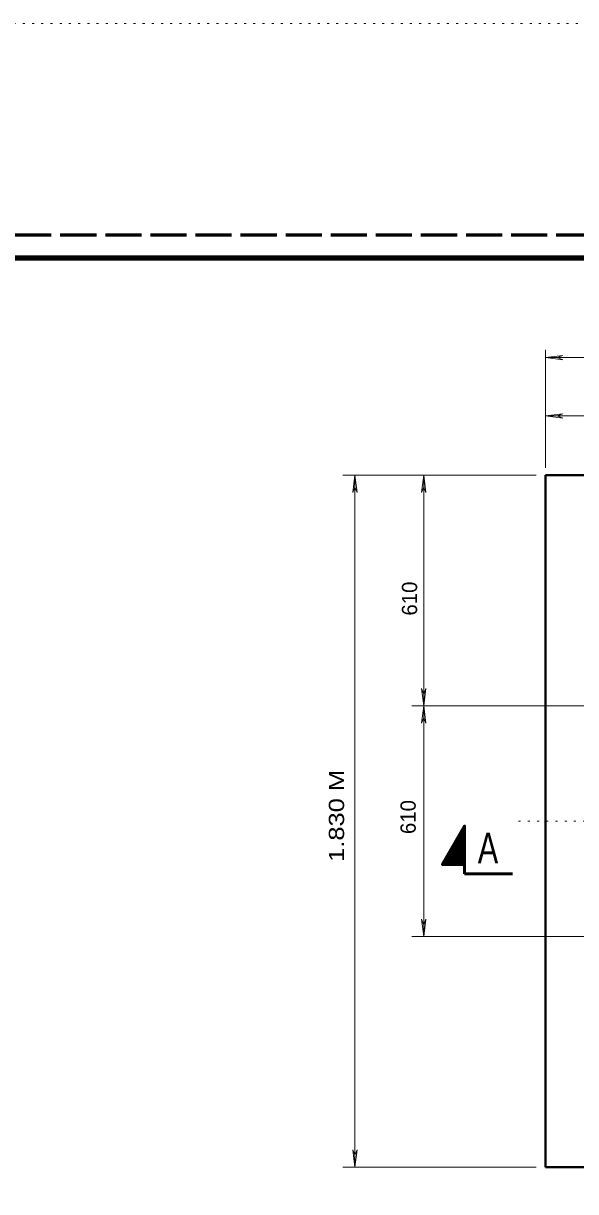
# Model space of a CAD drawing. Extents: x 312583 to 312854, y 144419 to 144597.
# Drawn here: x 312717.6 to 312745.2, y 144538.5 to 144596.8 of the extents above; entities that cross this region are included whole.
import ezdxf
from ezdxf.enums import TextEntityAlignment as Align

# ---------------------------------------------------------------- set-up
doc = ezdxf.new("R2010")
doc.units = 0
doc.header["$LTSCALE"] = 0.3
doc.linetypes.add('DOTTED', pattern=[1.5, 0.3, -1.2])
doc.linetypes.add('LONG_DASHED', pattern=[7.5, 6, -1.5])
for name, color, linetype, lineweight in [('1', 7, 'Continuous', 40), ('2', 7, 'Continuous', 13), ('62', 7, 'DOTTED', 13), ('63', 7, 'LONG_DASHED', 60)]:
    doc.layers.add(name, color=color, linetype=linetype, lineweight=lineweight)

msp = doc.modelspace()

# ---------------------------------------------------------------- linework, layer by layer
at = {"layer": '1'}
for p, q in [((312743.6593, 144574.2486), (312772.4093, 144574.2486)), ((312743.6593, 144574.2486), (312743.6593, 144539.7486)), ((312743.6593, 144539.7486), (312772.4093, 144539.7486))]:
    msp.add_line(p, q, dxfattribs=at)
at = {"layer": '1', "lineweight": 158}
msp.add_lwpolyline([(312616.5, 144423.1446), (312616.5, 144585.0846), (312849, 144585.0846)], dxfattribs=at)
at = {"layer": '2'}
for p, q in [((312743.6593, 144574.6243), (312743.6593, 144580.5046)), ((312743.6593, 144580.1213), (312744.5256, 144580.2286)), ((312743.6593, 144580.1213), (312772.4093, 144580.1213)), ((312743.6593, 144580.1213), (312744.5256, 144580.0139)), ((312744.5256, 144580.2286), (312744.2496, 144580.1213)), ((312744.5256, 144580.0139), (312744.2496, 144580.1213)), ((312743.6593, 144577.2079), (312744.5256, 144577.3153)), ((312743.6593, 144577.2079), (312744.5256, 144577.1006)), ((312744.5256, 144577.3153), (312744.2496, 144577.2079)), ((312744.5256, 144577.1006), (312744.2496, 144577.2079)), ((312743.1993, 144574.2486), (312733.5546, 144574.2486)), ((312734.1526, 144574.2486), (312734.0453, 144573.3823)), ((312734.1526, 144574.2486), (312734.1526, 144539.7486)), ((312734.1526, 144574.2486), (312734.26, 144573.3823)), ((312737.5873, 144574.2486), (312737.48, 144573.3823)), ((312737.5873, 144574.2486), (312737.6946, 144573.3823)), ((312734.0453, 144573.3823), (312734.1526, 144573.6583)), ((312734.26, 144573.3823), (312734.1526, 144573.6583)), ((312737.48, 144573.3823), (312737.5873, 144573.6583)), ((312737.6946, 144573.3823), (312737.5873, 144573.6583)), ((312737.48, 144563.6149), (312737.5873, 144563.3389)), ((312737.5873, 144562.7486), (312737.48, 144563.6149)), ((312737.6946, 144563.6149), (312737.5873, 144563.3389)), ((312737.5873, 144562.7486), (312737.6946, 144563.6149)), ((312751.74, 144562.7486), (312736.9893, 144562.7486)), ((312737.5873, 144562.7486), (312737.48, 144561.8823)), ((312737.5873, 144562.7486), (312737.6946, 144561.8823)), ((312737.48, 144561.8823), (312737.5873, 144562.1583)), ((312737.6946, 144561.8823), (312737.5873, 144562.1583)), ((312737.48, 144552.1149), (312737.5873, 144551.8389)), ((312737.5873, 144551.2486), (312737.48, 144552.1149)), ((312737.6946, 144552.1149), (312737.5873, 144551.8389)), ((312737.5873, 144551.2486), (312737.6946, 144552.1149)), ((312751.74, 144551.2486), (312736.9893, 144551.2486)), ((312734.0453, 144540.6149), (312734.1526, 144540.3389)), ((312734.1526, 144539.7486), (312734.0453, 144540.6149)), ((312734.26, 144540.6149), (312734.1526, 144540.3389)), ((312734.1526, 144539.7486), (312734.26, 144540.6149)), ((312743.1993, 144539.7486), (312733.5546, 144539.7486))]:
    msp.add_line(p, q, dxfattribs=at)
at = {"layer": '2', "lineweight": 35}
for p, q in [((312739.6266, 144556.4159), (312739.4733, 144556.5003)), ((312739.6266, 144556.4389), (312739.4886, 144556.5156)), ((312739.6266, 144556.4696), (312739.4963, 144556.5386)), ((312739.6266, 144556.4926), (312739.5116, 144556.5616)), ((312739.6266, 144556.5156), (312739.5193, 144556.5846)), ((312739.6266, 144556.5463), (312739.5346, 144556.5999)), ((312739.6266, 144556.5769), (312739.5423, 144556.6229)), ((312739.6266, 144556.6076), (312739.5576, 144556.6459)), ((312739.6266, 144556.6306), (312739.5653, 144556.6613)), ((312739.6266, 144556.6613), (312739.5806, 144556.6843)), ((312739.6266, 144556.6843), (312739.5883, 144556.7073)), ((312739.6266, 144556.7149), (312739.6036, 144556.7226)), ((312739.6266, 144556.7456), (312739.6113, 144556.7456)), ((312739.6266, 144555.6339), (312739.136, 144555.9176)), ((312739.6266, 144555.6646), (312739.1513, 144555.9406)), ((312739.6266, 144555.6953), (312739.159, 144555.9559)), ((312739.6266, 144555.7183), (312739.1743, 144555.9789)), ((312739.6266, 144555.7489), (312739.182, 144556.0019)), ((312739.6266, 144555.7796), (312739.1973, 144556.0173)), ((312739.6266, 144555.8026), (312739.205, 144556.0403)), ((312739.6266, 144555.8256), (312739.2203, 144556.0633)), ((312739.6266, 144555.8563), (312739.228, 144556.0863)), ((312739.6266, 144555.8869), (312739.2433, 144556.1016)), ((312739.6266, 144555.9176), (312739.2586, 144556.1246)), ((312739.6266, 144555.9406), (312739.2663, 144556.1476)), ((312739.6266, 144555.9713), (312739.2816, 144556.1629)), ((312739.6266, 144555.9943), (312739.297, 144556.1859)), ((312739.6266, 144556.0249), (312739.3046, 144556.2089)), ((312739.6266, 144556.0479), (312739.32, 144556.2243)), ((312739.6266, 144556.0786), (312739.3276, 144556.2473)), ((312739.6266, 144556.1093), (312739.343, 144556.2703)), ((312739.6266, 144556.1323), (312739.3506, 144556.2856)), ((312739.6266, 144556.1629), (312739.366, 144556.3163)), ((312739.6266, 144556.1859), (312739.3736, 144556.3316)), ((312739.6266, 144556.2166), (312739.389, 144556.3546)), ((312739.6266, 144556.2473), (312739.3966, 144556.3776)), ((312739.6266, 144556.2703), (312739.412, 144556.3929)), ((312739.6266, 144556.3009), (312739.4196, 144556.4159)), ((312739.6266, 144556.3239), (312739.435, 144556.4389)), ((312739.6266, 144556.3546), (312739.4503, 144556.4543)), ((312739.6266, 144556.3853), (312739.458, 144556.4773)), ((312739.6036, 144554.8443), (312738.791, 144555.3196)), ((312739.6266, 144554.8596), (312738.8063, 144555.3349)), ((312739.6266, 144554.8903), (312738.814, 144555.3579)), ((312739.6266, 144554.9209), (312738.8293, 144555.3809)), ((312739.6266, 144554.9439), (312738.837, 144555.3963)), ((312739.6266, 144554.9746), (312738.8523, 144555.4193)), ((312739.619, 144554.9976), (312738.86, 144555.4423)), ((312739.619, 144555.0283), (312738.8753, 144555.4576)), ((312739.6266, 144555.0513), (312738.883, 144555.4806)), ((312739.6266, 144555.0819), (312738.8983, 144555.5036)), ((312739.6266, 144555.1126), (312738.9136, 144555.5189)), ((312739.6266, 144555.1356), (312738.9213, 144555.5419)), ((312739.6266, 144555.1663), (312738.9366, 144555.5649)), ((312739.6266, 144555.1969), (312738.952, 144555.5879)), ((312739.6266, 144555.2199), (312738.9596, 144555.6033)), ((312739.619, 144555.2506), (312738.975, 144555.6263)), ((312739.6266, 144555.2813), (312738.9826, 144555.6493)), ((312739.6266, 144555.3043), (312738.998, 144555.6646)), ((312739.6266, 144555.3273), (312739.0056, 144555.6876)), ((312739.6266, 144555.3579), (312739.021, 144555.7106)), ((312739.6266, 144555.3886), (312739.0286, 144555.7259)), ((312739.6266, 144555.4193), (312739.044, 144555.7489)), ((312739.6266, 144555.4423), (312739.0516, 144555.7719)), ((312739.6266, 144555.4729), (312739.067, 144555.7873)), ((312739.619, 144555.4959), (312739.0746, 144555.8179)), ((312739.6266, 144555.5266), (312739.09, 144555.8333)), ((312739.6266, 144555.5496), (312739.1053, 144555.8563)), ((312739.6266, 144555.5803), (312739.113, 144555.8793)), ((312739.6266, 144555.6109), (312739.1283, 144555.8946)), ((312738.5456, 144554.8443), (312738.5303, 144554.8596)), ((312738.5916, 144554.8443), (312738.538, 144554.8826)), ((312738.6453, 144554.8443), (312738.5533, 144554.8979)), ((312738.6913, 144554.8443), (312738.5686, 144554.9209)), ((312738.745, 144554.8443), (312738.5763, 144554.9439)), ((312738.7833, 144554.8443), (312738.5916, 144554.9593)), ((312738.837, 144554.8443), (312738.5993, 144554.9823)), ((312738.883, 144554.8443), (312738.6146, 144555.0053)), ((312738.929, 144554.8443), (312738.6223, 144555.0206)), ((312738.975, 144554.8443), (312738.6376, 144555.0513)), ((312739.0286, 144554.8443), (312738.6453, 144555.0666)), ((312739.0746, 144554.8443), (312738.6606, 144555.0896)), ((312739.1206, 144554.8443), (312738.6683, 144555.1126)), ((312739.1743, 144554.8443), (312738.6836, 144555.1279)), ((312739.2203, 144554.8443), (312738.6913, 144555.1509)), ((312739.2663, 144554.8443), (312738.7066, 144555.1663)), ((312739.32, 144554.8443), (312738.722, 144555.1893)), ((312739.366, 144554.8443), (312738.7296, 144555.2123)), ((312739.412, 144554.8443), (312738.745, 144555.2276)), ((312739.458, 144554.8443), (312738.7603, 144555.2506)), ((312739.5116, 144554.8443), (312738.768, 144555.2736)), ((312739.55, 144554.8443), (312738.7833, 144555.2889))]:
    msp.add_line(p, q, dxfattribs=at)
at = {"layer": '2', "linetype": 'DOTTED'}
msp.add_line((312757.605, 144556.9986), (312742.0186, 144556.9986), dxfattribs=at)
at = {"layer": '2', "lineweight": 53}
for p in [(312739.6266, 144554.8443), (312742.0186, 144554.3689)]:
    msp.add_line(p, (312739.6266, 144554.3689), dxfattribs=at)
at = {"layer": '2'}
for points in [[(312743.6593, 144577.2079), (312752.2843, 144577.2079), (312763.7843, 144577.2079)], [(312737.5873, 144574.2486), (312737.5873, 144562.7486), (312737.5873, 144551.2486)]]:
    msp.add_lwpolyline(points, dxfattribs=at)
at = {"layer": '2', "lineweight": 53}
msp.add_lwpolyline([(312739.6266, 144554.8443), (312738.515, 144554.8443), (312739.6266, 144556.7609)], close=True, dxfattribs=at)
at = {"layer": '62'}
msp.add_line((312601.2, 144596.7846), (312853.5, 144596.7846), dxfattribs=at)
at = {"layer": '63'}
msp.add_line((312851.75, 144586.2246), (312583.526, 144586.2246), dxfattribs=at)

# ---------------------------------------------------------------- texts
at = {"layer": '2'}
for p in [(312737.2568, 144567.252), (312737.1866, 144556.3575)]:
    msp.add_text('610', height=0.76, rotation=90, dxfattribs=at).set_placement(p)
at = {"layer": '2', "width": 1.25}
msp.add_text('1.830 M', height=0.76, rotation=90, dxfattribs=at).set_placement((312733.6118, 144554.9684))
at = {"layer": '2', "width": 0.75}
msp.add_text('A', height=1.533, dxfattribs=at).set_placement((312740.7958, 144554.8903), align=Align.CENTER)

doc.saveas('drawing.dxf')
